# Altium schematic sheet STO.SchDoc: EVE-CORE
size A4; Organization: Ingenia Motion Control; Address1: Carrer Avila, 124, 2B; Address2: 08018 Barcelona Spain; Address3: www.ingeniamc.com; Address4: www.ingeniamc.com; Documentation: https://doc.ingeniamc.com/x/coAZBg
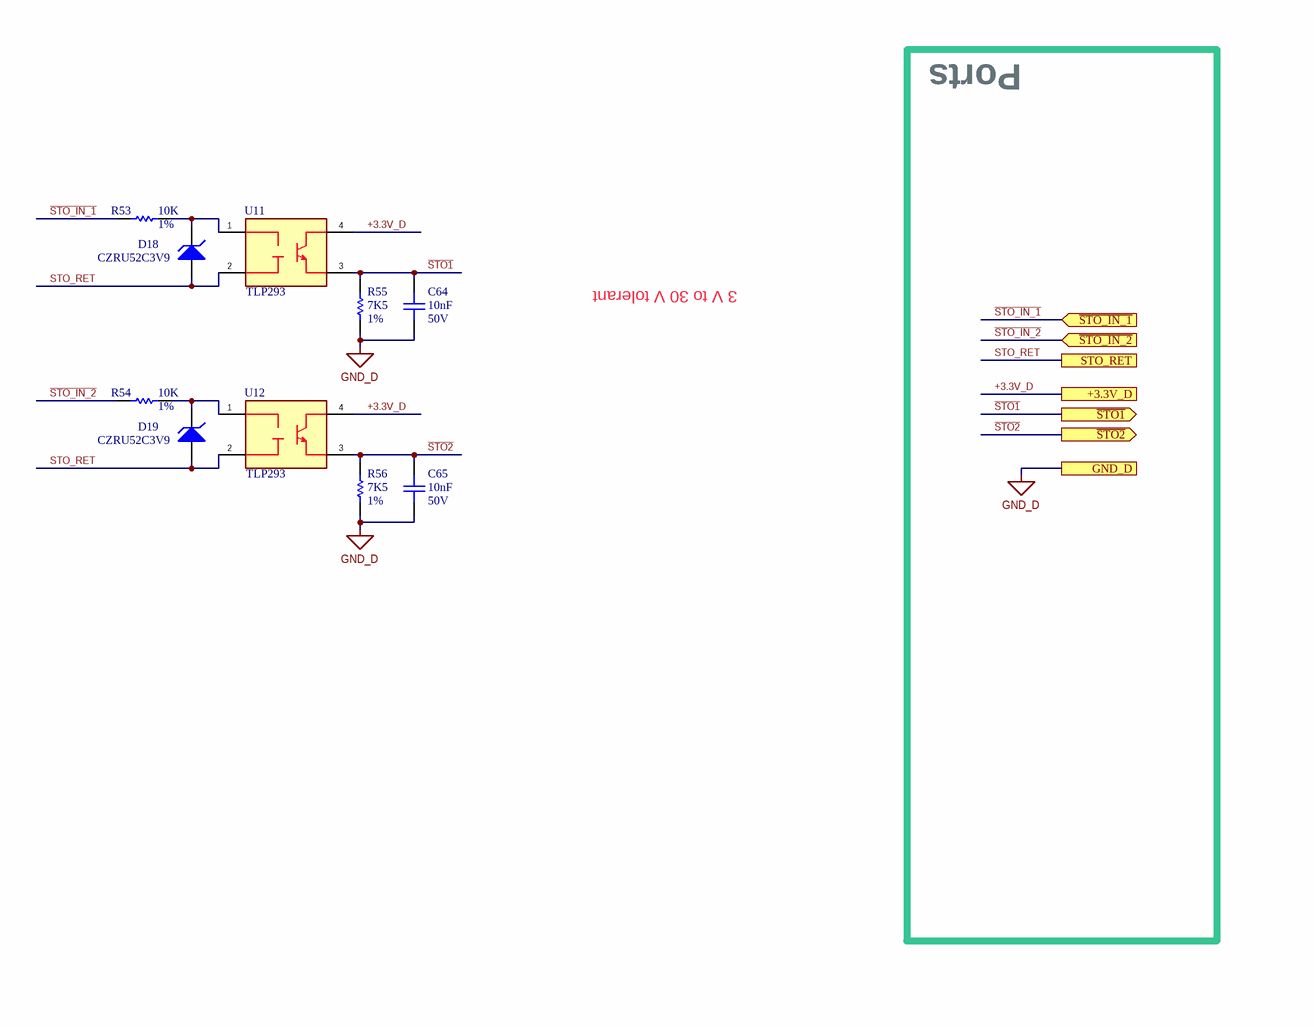
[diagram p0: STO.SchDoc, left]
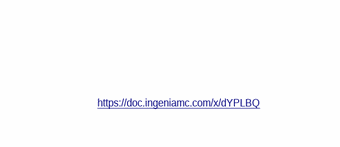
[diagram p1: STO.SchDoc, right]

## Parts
C64  value 10nF  Voltage: 50V  [C_0402HD]  (hidden comment: C_0402--10nF--50V)
C65  value 10nF  Voltage: 50V  [C_0402HD]  (hidden comment: C_0402--10nF--50V)
D18  CZRU52C3V9  [D_0603]
D19  CZRU52C3V9  [D_0603]
R53  value 10K  Tolerance: 1%  [R_0805]  (hidden comment: R_0805HV--10K--1%)
R54  value 10K  Tolerance: 1%  [R_0805]  (hidden comment: R_0805HV--10K--1%)
R55  value 7K5  Tolerance: 1%  [R_0402]  (hidden comment: R_0402--7K5--1%)
R56  value 7K5  Tolerance: 1%  [R_0402]  (hidden comment: R_0402--7K5--1%)
U11  TLP293  [SO4_H2.0mm]
U12  TLP293  [SO4_H2.0mm]

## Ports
+3.3V_D, GND_D, STO_RET, ~{STO1} (out), ~{STO2} (out), ~{STO_IN_1} (in), ~{STO_IN_2} (in)

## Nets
GND_D: C64.2 C65.2 R55.2 R56.2 ; port GND_D
+3.3V_D: U11.4 U12.4 ; port +3.3V_D
~{STO1}: C64.1 R55.1 U11.3 ; port ~{STO1}
~{STO2}: C65.1 R56.1 U12.3 ; port ~{STO2}
~{STO_IN_1}: R53.1 ; port ~{STO_IN_1}
~{STO_IN_2}: R54.1 ; port ~{STO_IN_2}
STO_RET: D18.1(A) D19.1(A) U11.2 U12.2 ; port STO_RET
NetD18_2: D18.2(K) R53.2 U11.1
NetD19_2: D19.2(K) R54.2 U12.1

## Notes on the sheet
- Ports
- 3 V to 30 V tolerant
- https://doc.ingeniamc.com/x/dYPLBQ

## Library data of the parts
C64 C65 = C_0402[[/\]]10nF[[/\]]50V: CAP CER 10nF 50V X7R 0402; Part Number: C_0402; ManufacturerName: KEMET; ManufacturerPN: C0402C103K5RACTU; AlternativeManufacturer: TDK Corporation; IsPreferred: 0; IngeniaID: 3723; TemperatureMaxC: 125; TemperatureMinC: -55; AlternativePN: C1005X8R1H103K050BB
D18 D19 = CZRU52C3V9: DIODE ZENER 0.15W 5% 0603. 3.9 V @ 5mA, 3.3 V @ 1mA; ManufacturerName: Comchip; Value: 3.9V; IsPreferred: 0; IngeniaID: 4532
R53 R54 = R_0805HV[[/\]]10K[[/\]]1%: Resistor, 0805, 10kohm, 1/2 W, 400V; ManufacturerName: Panasonic; ManufacturerPN: ERJ-P06F1002V; IsPreferred: 0; IngeniaID: 2844; TemperatureMaxC: 155; TemperatureMinC: -55
R55 R56 = R_0402[[/\]]7K5[[/\]]1%: RESISTOR 7.5 K OHM 1/16W 1% 0402 SMD; ManufacturerName: Stackpole Electronics; ManufacturerPN: RMCF0402FT7K50; IsPreferred: 0; IngeniaID: 5193; TemperatureMaxC: 155; TemperatureMinC: -55
U11 U12 = TLP293: Transistor Output Optocoupler, 125 ºC, 3750Vrms isolation, 50% Min CTR; ManufacturerName: Toshiba; ManufacturerPN: TLP293(BL-TPL,E; AlternativeManufacturer: ON Semiconductor; IsPreferred: 0; IngeniaID: 2870; TemperatureMaxC: 125; TemperatureMinC: -55; AlternativePN: FODM8801CV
